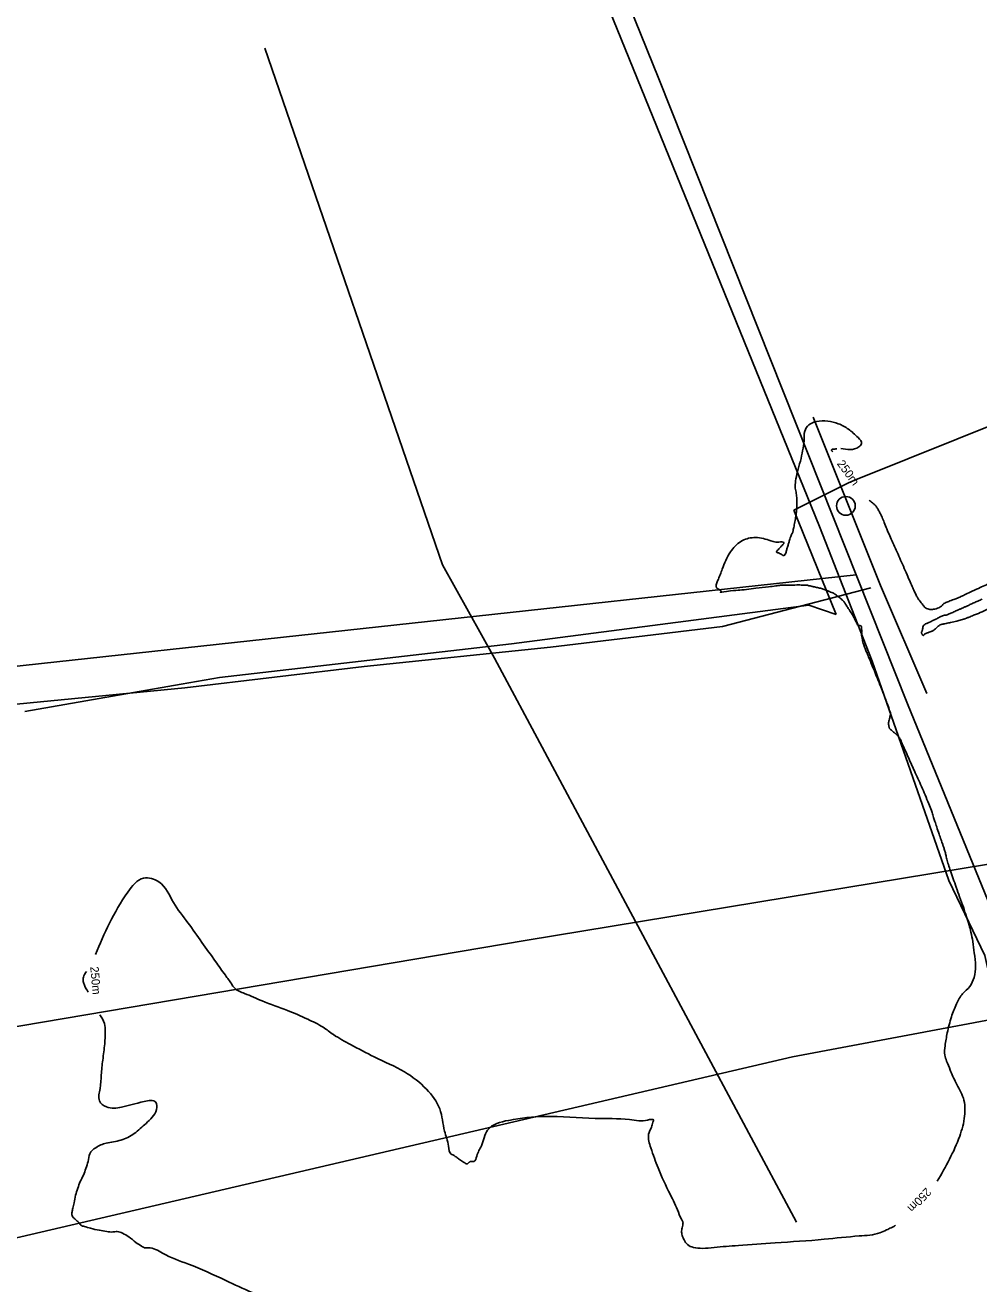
# Model space of a CAD drawing. Extents: x -478495 to -472450, y -1118050 to -1113745.
# Drawn here: x -476105.4 to -475901.4, y -1117333.3 to -1117063.9 of the extents above; entities that cross this region are included whole.
import ezdxf

# ---------------------------------------------------------------- set-up
doc = ezdxf.new("R2010")
doc.units = 0
for name, color, linetype in [('cesty', 7, 'Continuous'), ('cyklostezka', 7, 'Continuous'), ('el vedeni_NN', 7, 'Continuous'), ('el vedeni_VVN', 7, 'Continuous'), ('ObPÚ', 7, 'Continuous'), ('silnice', 7, 'Continuous'), ('Vrstevnice_hlavni', 7, 'Continuous'), ('Vrstevnice_popis', 7, 'Continuous')]:
    doc.layers.add(name, color=color, linetype=linetype)

msp = doc.modelspace()

# ---------------------------------------------------------------- linework, layer by layer
at = {"layer": 'cesty'}
msp.add_circle((-475929.86, -1117166.81), 2, dxfattribs=at)
at = {"layer": 'cyklostezka'}
msp.add_lwpolyline([(-476254.27, -1116156.47), (-476222.18, -1116232.89), (-476211.78, -1116254.37), (-476202.07, -1116276.08), (-476175.63, -1116319.27), (-476155.29, -1116349.34), (-476145.57, -1116374.89), (-476134.72, -1116405.19), (-476127.72, -1116444.76), (-476107.83, -1116579.35), (-476095.96, -1116657.36), (-476085.23, -1116737.63), (-476059.24, -1116863.13), (-475998.22, -1117016.88), (-475935.51, -1117171.2), (-475924.21, -1117200.03), (-475907.82, -1117246.95), (-475900.14, -1117263), (-475894.04, -1117290.14), (-475894.94, -1117318.4), (-475960.16, -1117684.94)], dxfattribs=at)
at = {"layer": 'el vedeni_NN'}
for points in [[(-476054.13, -1117068.87), (-476016.19, -1117179.43), (-476005.06, -1117199.42), (-475940.42, -1117320.09)], [(-475936.88, -1117147.84), (-475922.46, -1117183.82), (-475912.51, -1117206.96)], [(-476142.53, -1117233.56), (-476143.47, -1117231.01), (-476140.29, -1117228.14), (-476109.49, -1117209.47), (-476071.25, -1117205.72), (-476032.93, -1117201.19), (-475993.05, -1117197.05), (-475956.25, -1117192.65), (-475924.55, -1117184.37)]]:
    msp.add_lwpolyline(points, dxfattribs=at)
at = {"layer": 'el vedeni_VVN'}
for points in [[(-475331.25, -1117150.77), (-475502.65, -1117177.68), (-475743.53, -1117217.8), (-475998.47, -1117259.85), (-476243.03, -1117301.16), (-476372.5, -1117439.24)], [(-475331.25, -1117150.77), (-475502.65, -1117177.68), (-475743.53, -1117217.8), (-475998.47, -1117259.85), (-476243.03, -1117301.16), (-476372.5, -1117439.24)], [(-476280.71, -1117409.3), (-476225.71, -1117351.08), (-475941.31, -1117284.75), (-475941.31, -1117284.75), (-475650.16, -1117229.98), (-475650.16, -1117229.98), (-475374.72, -1117181.71), (-475324.35, -1117172.68)], [(-476280.71, -1117409.3), (-476225.71, -1117351.08), (-475941.31, -1117284.75), (-475941.31, -1117284.75), (-475650.16, -1117229.98), (-475650.16, -1117229.98), (-475374.72, -1117181.71), (-475324.35, -1117172.68)]]:
    msp.add_lwpolyline(points, dxfattribs=at)
at = {"layer": 'ObPÚ'}
for p, q in [((-475927.44, -1117161.1), (-475878.72, -1117141.49)), ((-475878.72, -1117141.49), (-475927.44, -1117161.1)), ((-475929.26, -1117161.85), (-475927.44, -1117161.1)), ((-475927.44, -1117161.1), (-475929.26, -1117161.85)), ((-475941.01, -1117167.72), (-475929.26, -1117161.85)), ((-475929.26, -1117161.85), (-475941.01, -1117167.72)), ((-475931.93, -1117190.03), (-475941.01, -1117167.72)), ((-475941.01, -1117167.72), (-475931.93, -1117190.03)), ((-476001.41, -1117196.31), (-475937.76, -1117188.08)), ((-475937.76, -1117188.08), (-476001.41, -1117196.31)), ((-475937.76, -1117188.08), (-475931.93, -1117190.03)), ((-475931.93, -1117190.03), (-475937.76, -1117188.08)), ((-476063.89, -1117203.52), (-476001.41, -1117196.31)), ((-476001.41, -1117196.31), (-476063.89, -1117203.52)), ((-476072.1, -1117204.95), (-476063.89, -1117203.52)), ((-476063.89, -1117203.52), (-476072.1, -1117204.95)), ((-476099.81, -1117209.8), (-476072.1, -1117204.95)), ((-476072.1, -1117204.95), (-476099.81, -1117209.8)), ((-476105.51, -1117210.79), (-476099.81, -1117209.8)), ((-476099.81, -1117209.8), (-476105.51, -1117210.79))]:
    msp.add_line(p, q, dxfattribs=at)
at = {"layer": 'silnice'}
for points in [[(-475903.98, -1117378.32), (-475889.52, -1117318.18), (-475888.39, -1117289.01), (-475895.39, -1117261.2), (-475916.64, -1117209.19), (-475969.89, -1117075.46), (-476021.05, -1116948.74), (-476052.92, -1116863.98), (-476081.44, -1116727.19), (-476114.99, -1116491.38), (-476128.41, -1116405.78), (-476137.64, -1116368.02), (-476162.8, -1116322.7), (-476200.54, -1116268.15), (-476239.96, -1116179.2)], [(-476503.76, -1117230.5), (-476424.07, -1117228.82), (-476282.32, -1117220.43), (-476211.03, -1117212.03), (-476122.96, -1117202.8), (-476029.86, -1117192.73), (-475927.64, -1117181.55)]]:
    msp.add_lwpolyline(points, dxfattribs=at)
at = {"layer": 'Vrstevnice_hlavni'}
for points in [[(-475924.87, -1117165.58), (-475924.18, -1117166.16), (-475923.89, -1117166.41), (-475923.67, -1117166.6), (-475923.51, -1117166.75), (-475923.27, -1117167.08), (-475922.96, -1117167.61), (-475922.57, -1117168.32), (-475922.12, -1117169.25), (-475921.63, -1117170.4), (-475921.08, -1117171.76), (-475920.47, -1117173.2), (-475919.8, -1117174.72), (-475919.07, -1117176.31), (-475918.33, -1117177.98), (-475917.56, -1117179.73), (-475916.77, -1117181.55), (-475916.09, -1117183.09), (-475915.54, -1117184.35), (-475915.1, -1117185.31), (-475914.71, -1117186.1), (-475914.36, -1117186.7), (-475914.06, -1117187.12), (-475913.73, -1117187.56), (-475913.38, -1117188), (-475913, -1117188.46), (-475912.58, -1117188.77), (-475912.12, -1117188.95), (-475911.61, -1117188.99), (-475911.09, -1117188.94), (-475910.54, -1117188.81), (-475909.97, -1117188.6), (-475909.54, -1117188.38), (-475909.26, -1117188.15), (-475909.11, -1117187.91), (-475908.65, -1117187.61), (-475907.86, -1117187.25), (-475906.76, -1117186.84), (-475905.96, -1117186.53), (-475905.45, -1117186.32), (-475905.24, -1117186.23), (-475904.51, -1117185.88), (-475903.25, -1117185.29), (-475901.46, -1117184.46), (-475900.15, -1117183.86), (-475899.3, -1117183.5), (-475898.92, -1117183.37), (-475898.52, -1117183.21), (-475898.08, -1117183.03), (-475897.61, -1117182.82), (-475896.49, -1117182.35), (-475894.71, -1117181.62), (-475892.28, -1117180.62), (-475890.54, -1117179.9), (-475889.51, -1117179.48), (-475889.18, -1117179.33), (-475888.26, -1117178.81), (-475886.76, -1117177.91), (-475884.67, -1117176.62), (-475883.24, -1117175.73), (-475882.45, -1117175.24), (-475882.32, -1117175.15), (-475882.19, -1117175.06), (-475882.07, -1117175), (-475881.97, -1117174.94), (-475881.4, -1117174.62), (-475880.38, -1117174.03), (-475878.9, -1117173.17), (-475877.91, -1117172.59), (-475877.41, -1117172.31), (-475877.4, -1117172.3), (-475877.37, -1117172.3), (-475877.33, -1117172.3), (-475877.28, -1117172.3), (-475877.17, -1117172.27), (-475877, -1117172.22), (-475876.76, -1117172.15), (-475876.42, -1117171.76), (-475875.99, -1117171.07), (-475875.47, -1117170.08), (-475874.91, -1117168.9), (-475874.32, -1117167.54), (-475873.69, -1117166), (-475873.61, -1117163.3), (-475874.08, -1117159.45), (-475875.1, -1117154.44), (-475875.87, -1117150.69), (-475876.39, -1117148.21), (-475876.67, -1117147), (-475877.26, -1117145.76), (-475878.15, -1117144.49), (-475879.35, -1117143.19), (-475880.24, -1117142.16), (-475880.82, -1117141.4), (-475881.08, -1117140.91), (-475881.42, -1117139.94), (-475881.82, -1117138.49)], [(-475930.92, -1117154.53), (-475927.09, -1117154.2), (-475926.5, -1117153.48), (-475927.24, -1117152.21), (-475929.3, -1117150.4), (-475931.47, -1117149.22), (-475933.75, -1117148.67), (-475936.13, -1117148.75), (-475937.77, -1117149.48), (-475938.66, -1117150.86), (-475938.8, -1117152.87), (-475939.11, -1117155), (-475939.59, -1117157.22), (-475940.24, -1117159.55), (-475940.6, -1117161.48), (-475940.68, -1117163.02), (-475940.47, -1117164.15), (-475940.35, -1117165.28), (-475940.32, -1117166.41), (-475940.38, -1117167.54), (-475940.51, -1117168.71), (-475940.7, -1117169.92), (-475940.95, -1117171.18), (-475941.16, -1117172.1), (-475941.34, -1117172.7), (-475941.47, -1117172.96), (-475941.64, -1117173.39), (-475941.84, -1117173.97), (-475942.07, -1117174.7), (-475942.29, -1117175.44), (-475942.51, -1117176.18), (-475942.72, -1117176.91), (-475942.98, -1117177.33), (-475943.31, -1117177.41), (-475943.69, -1117177.18), (-475944.03, -1117177), (-475944.3, -1117176.87), (-475944.53, -1117176.81), (-475944.67, -1117176.74), (-475944.73, -1117176.68), (-475944.71, -1117176.61), (-475944.52, -1117176.38), (-475944.17, -1117176), (-475943.67, -1117175.45), (-475943.32, -1117175.07), (-475943.14, -1117174.85), (-475943.13, -1117174.79), (-475944.2, -1117174.56), (-475946.35, -1117174.16), (-475949.57, -1117173.59), (-475952.31, -1117174.42), (-475954.55, -1117176.67), (-475956.31, -1117180.33), (-475957.29, -1117182.88), (-475957.51, -1117184.34), (-475956.96, -1117184.71), (-475956.63, -1117184.97), (-475956.52, -1117185.15), (-475956.64, -1117185.23), (-475955.43, -1117185.14), (-475952.92, -1117184.88), (-475949.1, -1117184.45), (-475946.4, -1117184.14), (-475944.84, -1117183.94), (-475944.41, -1117183.87), (-475944.03, -1117183.82), (-475943.69, -1117183.79), (-475943.4, -1117183.79), (-475942.69, -1117183.78), (-475941.55, -1117183.76), (-475939.99, -1117183.74), (-475938.84, -1117183.75), (-475938.1, -1117183.8), (-475937.77, -1117183.89), (-475937.27, -1117184.01), (-475936.58, -1117184.16), (-475935.71, -1117184.34), (-475934.89, -1117184.57), (-475934.11, -1117184.83), (-475933.38, -1117185.14), (-475932.84, -1117185.37), (-475932.5, -1117185.51), (-475932.35, -1117185.58), (-475932.07, -1117185.78), (-475931.66, -1117186.11), (-475931.1, -1117186.56), (-475930.69, -1117186.91), (-475930.43, -1117187.14), (-475930.32, -1117187.27), (-475930.1, -1117187.58), (-475929.77, -1117188.07), (-475929.33, -1117188.75), (-475928.98, -1117189.29), (-475928.73, -1117189.68), (-475928.57, -1117189.92), (-475928.36, -1117190.29), (-475928.09, -1117190.79)], [(-475932.65, -1117155.22), (-475932.92, -1117154.88), (-475932.88, -1117154.76), (-475932.65, -1117154.68), (-475931.82, -1117154.61)], [(-475875.8, -1117199.97), (-475875.68, -1117202.4), (-475875.66, -1117203.36), (-475875.67, -1117204.05), (-475875.73, -1117204.49), (-475875.92, -1117205.28), (-475876.26, -1117206.42), (-475876.74, -1117207.92), (-475877.25, -1117208.5), (-475877.79, -1117208.17), (-475878.35, -1117206.93), (-475878.8, -1117205.98), (-475879.14, -1117205.32), (-475879.36, -1117204.94), (-475880.4, -1117204.05), (-475882.26, -1117202.63), (-475884.95, -1117200.7), (-475887.69, -1117198.18), (-475890.49, -1117195.07), (-475893.35, -1117191.37), (-475896, -1117189.2), (-475898.45, -1117188.57), (-475900.7, -1117189.48), (-475902.31, -1117190.13), (-475903.29, -1117190.53), (-475903.64, -1117190.67), (-475903.92, -1117190.79), (-475904.14, -1117190.87), (-475904.28, -1117190.93), (-475904.42, -1117190.98), (-475904.55, -1117191.03), (-475904.68, -1117191.08), (-475905.2, -1117191.22), (-475906.13, -1117191.45), (-475907.46, -1117191.76), (-475908.39, -1117191.97), (-475908.93, -1117192.09), (-475909.08, -1117192.1), (-475909.23, -1117192.13), (-475909.38, -1117192.17), (-475909.53, -1117192.21), (-475909.67, -1117192.27), (-475909.79, -1117192.34), (-475909.9, -1117192.42), (-475910.09, -1117192.58), (-475910.36, -1117192.82), (-475910.71, -1117193.14), (-475911.02, -1117193.38), (-475911.28, -1117193.55), (-475911.5, -1117193.64), (-475911.68, -1117193.72), (-475911.84, -1117193.78), (-475911.95, -1117193.82), (-475912.15, -1117193.9), (-475912.41, -1117194.01), (-475912.75, -1117194.15), (-475913, -1117194.27), (-475913.15, -1117194.39), (-475913.21, -1117194.49), (-475913.28, -1117194.53), (-475913.35, -1117194.52), (-475913.44, -1117194.45), (-475913.51, -1117194.35), (-475913.59, -1117194.21), (-475913.66, -1117194.04), (-475913.68, -1117193.9), (-475913.65, -1117193.78), (-475913.58, -1117193.69), (-475913.51, -1117193.48), (-475913.44, -1117193.17), (-475913.37, -1117192.75), (-475913.22, -1117192.41), (-475912.97, -1117192.17), (-475912.64, -1117192.01), (-475912.37, -1117191.89), (-475912.16, -1117191.8), (-475912.02, -1117191.76), (-475911.88, -1117191.7), (-475911.73, -1117191.62), (-475911.59, -1117191.54), (-475911.22, -1117191.34), (-475910.63, -1117191.05), (-475909.83, -1117190.65), (-475909.19, -1117190.37), (-475908.72, -1117190.22), (-475908.41, -1117190.19), (-475907.9, -1117190.02), (-475907.2, -1117189.73), (-475906.31, -1117189.3), (-475905.57, -1117188.95), (-475904.99, -1117188.69), (-475904.57, -1117188.51), (-475904.01, -1117188.26), (-475903.3, -1117187.95), (-475902.46, -1117187.56), (-475901.59, -1117187.18), (-475900.71, -1117186.78)], [(-475928.09, -1117190.79), (-475927.77, -1117191.42), (-475927.55, -1117191.88), (-475927.42, -1117192.16), (-475927.39, -1117192.27), (-475927.32, -1117192.34), (-475927.2, -1117192.39), (-475927.04, -1117192.4), (-475926.88, -1117192.42), (-475926.74, -1117192.45), (-475926.61, -1117192.48), (-475926.53, -1117192.71), (-475926.48, -1117193.11), (-475926.47, -1117193.71), (-475926.47, -1117194.12), (-475926.49, -1117194.33), (-475926.52, -1117194.36), (-475926.53, -1117194.41), (-475926.52, -1117194.47), (-475926.48, -1117194.55), (-475926.43, -1117194.79), (-475926.36, -1117195.18), (-475926.27, -1117195.71), (-475926.13, -1117196.28), (-475925.92, -1117196.88), (-475925.67, -1117197.52), (-475925.32, -1117198.36), (-475924.88, -1117199.42), (-475924.35, -1117200.69), (-475923.76, -1117202.13), (-475923.11, -1117203.74), (-475922.4, -1117205.52), (-475921.8, -1117207.04), (-475921.33, -1117208.28), (-475920.97, -1117209.25), (-475920.69, -1117210.01), (-475920.5, -1117210.57), (-475920.38, -1117210.92), (-475920.31, -1117211.2), (-475920.29, -1117211.41), (-475920.32, -1117211.55), (-475920.37, -1117211.8), (-475920.47, -1117212.17), (-475920.59, -1117212.67), (-475920.68, -1117213.02), (-475920.73, -1117213.25), (-475920.75, -1117213.33), (-475920.74, -1117213.49), (-475920.7, -1117213.72), (-475920.65, -1117214.01), (-475920.6, -1117214.24), (-475920.55, -1117214.38), (-475920.51, -1117214.46), (-475920.37, -1117214.61), (-475920.12, -1117214.83), (-475919.78, -1117215.12), (-475919.5, -1117215.34), (-475919.3, -1117215.49), (-475919.17, -1117215.56), (-475918.99, -1117215.72), (-475918.77, -1117215.97), (-475918.49, -1117216.31), (-475918.28, -1117216.63), (-475918.11, -1117216.92), (-475918, -1117217.2), (-475917.71, -1117217.88), (-475917.24, -1117218.95), (-475916.59, -1117220.43), (-475915.91, -1117221.96), (-475915.19, -1117223.54), (-475914.43, -1117225.18), (-475913.67, -1117226.89), (-475912.9, -1117228.68), (-475912.13, -1117230.55), (-475911.57, -1117231.97), (-475911.22, -1117232.94), (-475911.08, -1117233.47), (-475910.81, -1117234.33), (-475910.42, -1117235.52), (-475909.9, -1117237.04), (-475909.47, -1117238.28), (-475909.14, -1117239.24), (-475908.91, -1117239.92), (-475908.69, -1117240.67), (-475908.47, -1117241.5), (-475908.26, -1117242.39), (-475907.93, -1117243.54), (-475907.47, -1117244.94), (-475906.89, -1117246.59), (-475906.24, -1117248.44), (-475905.52, -1117250.48), (-475904.72, -1117252.72), (-475904.05, -1117254.73), (-475903.51, -1117256.51), (-475903.09, -1117258.07), (-475902.72, -1117260.05), (-475902.4, -1117262.47)], [(-476090.42, -1117262.79), (-476083.47, -1117249.45), (-476080.11, -1117246.5), (-476076.84, -1117247.25), (-476073.69, -1117251.71), (-476070.61, -1117256.04), (-476067.63, -1117260.23), (-476064.73, -1117264.29), (-476062.61, -1117267.26), (-476061.26, -1117269.15), (-476060.68, -1117269.95), (-476058.5, -1117271.15), (-476054.72, -1117272.76), (-476049.34, -1117274.78), (-476045, -1117276.66), (-476041.71, -1117278.39), (-476039.47, -1117279.97), (-476035.81, -1117282.09), (-476030.74, -1117284.75), (-476024.26, -1117287.94), (-476019.59, -1117291.64), (-476016.74, -1117295.86), (-476015.71, -1117300.6), (-476014.89, -1117303.82), (-476014.31, -1117305.52), (-476013.95, -1117305.7), (-476013.41, -1117306.03), (-476012.71, -1117306.52), (-476011.84, -1117307.15), (-476011.21, -1117307.52), (-476010.82, -1117307.63), (-476010.68, -1117307.47), (-476010.53, -1117307.34), (-476010.38, -1117307.23), (-476010.21, -1117307.15), (-476010.01, -1117307.1), (-476009.76, -1117307.08), (-476009.47, -1117307.08), (-476008.83, -1117305.97), (-476007.84, -1117303.75), (-476006.5, -1117300.4), (-476001.99, -1117298.31), (-475994.32, -1117297.48), (-475983.49, -1117297.91), (-475976.14, -1117298.16), (-475972.27, -1117298.24), (-475971.89, -1117298.14), (-475971.56, -1117298.1), (-475971.29, -1117298.1), (-475971.08, -1117298.15), (-475971.14, -1117298.7), (-475971.46, -1117299.75), (-475972.05, -1117301.3), (-475971.58, -1117304.22), (-475970.04, -1117308.5), (-475967.44, -1117314.14), (-475965.69, -1117317.94), (-475964.78, -1117319.9), (-475964.71, -1117320.02), (-475964.72, -1117320.41), (-475964.82, -1117321.06), (-475965, -1117321.99), (-475964.88, -1117322.93), (-475964.47, -1117323.91), (-475963.76, -1117324.91), (-475962.45, -1117325.51), (-475960.54, -1117325.7), (-475958.04, -1117325.5), (-475952.86, -1117325.11), (-475945.01, -1117324.53), (-475934.49, -1117323.77), (-475927, -1117323.05), (-475922.56, -1117322.38), (-475921.15, -1117321.75), (-475920.17, -1117321.31), (-475919.63, -1117321.05), (-475919.52, -1117320.97), (-475919.42, -1117320.9), (-475919.34, -1117320.83), (-475919.23, -1117320.73)], [(-475902.4, -1117262.47), (-475902.12, -1117265.3), (-475902.44, -1117267.71), (-475903.35, -1117269.67), (-475904.87, -1117271.2), (-475906.17, -1117273.37), (-475907.27, -1117276.17), (-475908.16, -1117279.61), (-475908.63, -1117282.33), (-475908.68, -1117284.33), (-475908.3, -1117285.61), (-475907.52, -1117287.57), (-475906.32, -1117290.22), (-475904.72, -1117293.55), (-475904.45, -1117297.38), (-475905.51, -1117301.7), (-475910.29, -1117311.34)], [(-476091.96, -1117270.9), (-476092.85, -1117269.18), (-476093.04, -1117268.4), (-476092.98, -1117267.7), (-476092.34, -1117266.47)], [(-476089.45, -1117275.71), (-476088.49, -1117277.56), (-476088.31, -1117279.33), (-476088.42, -1117281.95), (-476088.84, -1117285.4), (-476089.16, -1117288.58), (-476089.4, -1117291.49), (-476089.55, -1117294.11), (-476088.04, -1117295.45), (-476084.86, -1117295.51), (-476080.01, -1117294.28), (-476077.51, -1117294.45), (-476077.37, -1117296.01), (-476079.58, -1117298.95), (-476082.1, -1117301.13), (-476084.95, -1117302.55), (-476088.1, -1117303.19), (-476090.33, -1117304.16), (-476091.62, -1117305.46), (-476091.98, -1117307.08), (-476092.44, -1117308.61), (-476092.99, -1117310.05), (-476093.64, -1117311.41), (-476094.19, -1117312.84), (-476094.64, -1117314.35), (-476094.99, -1117315.94), (-476095.25, -1117317.13), (-476095.42, -1117317.91), (-476095.49, -1117318.3), (-476095.39, -1117318.69), (-476095.14, -1117319.08), (-476094.72, -1117319.48), (-476094.4, -1117319.79), (-476094.18, -1117319.99), (-476094.06, -1117320.1), (-476093.92, -1117320.26), (-476093.75, -1117320.46), (-476093.55, -1117320.72), (-476092.78, -1117321.03), (-476091.45, -1117321.4), (-476089.55, -1117321.84), (-476087.97, -1117322.11), (-476086.7, -1117322.2), (-476085.75, -1117322.11), (-476084.6, -1117322.46), (-476083.27, -1117323.23), (-476081.76, -1117324.43), (-476080.55, -1117325.23), (-476079.67, -1117325.62), (-476079.09, -1117325.59), (-476076.04, -1117326.75), (-476070.52, -1117329.08), (-476062.53, -1117332.58), (-476056.9, -1117335.14), (-476053.62, -1117336.75), (-476052.71, -1117337.42), (-476051.46, -1117338.48), (-476049.86, -1117339.93), (-476047.92, -1117341.77), (-476046.59, -1117342.96), (-476045.87, -1117343.5), (-476045.76, -1117343.39), (-476045.38, -1117343.22), (-476044.74, -1117342.99), (-476043.83, -1117342.7), (-476042.8, -1117344.12), (-476041.64, -1117347.26), (-476040.36, -1117352.12), (-476039.49, -1117355.38), (-476039.06, -1117357.03), (-476039.04, -1117357.07), (-476038.88, -1117357.46), (-476038.57, -1117358.2), (-476038.11, -1117359.29), (-476037.79, -1117360.1), (-476037.62, -1117360.61), (-476037.6, -1117360.85), (-476037.55, -1117362.23), (-476037.46, -1117364.76), (-476037.34, -1117368.43), (-476037.18, -1117371.37), (-476037, -1117373.57), (-476036.79, -1117375.03), (-476036.36, -1117376.01), (-476035.7, -1117376.52), (-476034.81, -1117376.56), (-476034.18, -1117376.57), (-476033.79, -1117376.55), (-476033.66, -1117376.51), (-476033.55, -1117376.49), (-476033.47, -1117376.5), (-476033.41, -1117376.53), (-476032.7, -1117376.46), (-476031.34, -1117376.29), (-476029.33, -1117376.03), (-476027.77, -1117375.82), (-476026.65, -1117375.66)]]:
    msp.add_spline(points, degree=3, dxfattribs=at)

# ---------------------------------------------------------------- texts
at = {"layer": 'Vrstevnice_popis'}
for height, rotation, p in [(1.799, 306.45, (-475932.25, -1117157.27)), (1.8, 274.9474, (-476091.58, -1117264.79)), (1.8, 226.3664, (-475912.23, -1117312.1))]:
    msp.add_text(' 250m ', height=height, rotation=rotation, dxfattribs=at).set_placement(p)

doc.saveas('drawing.dxf')
